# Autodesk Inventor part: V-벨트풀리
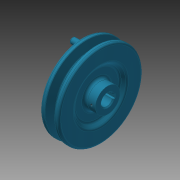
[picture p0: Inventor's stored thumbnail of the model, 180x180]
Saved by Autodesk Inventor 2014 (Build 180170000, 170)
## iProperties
Company: 한국ATC센터
Created: 2015-12
Part Number: V-벨트풀리
Document SubType Name: Modeling
Designer: mdu
Density: 7.25 g/cm^3
Mass: 596.622 g
Surface Area: 212.232 cm^2
Volume: 82.2927 cm^3
Material: 주철
Appearance: 터키옥색
Author: mdu
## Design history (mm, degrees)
sketch "스케치1"
  geometry: L1 (-13, 0)-(13, 0); L2 (-13, 0)-(-13, 12.5); L3 (-13, 12.5)-(-9, 12.5); L4 (-9, 12.5)-(-9, 23); L5 (-9, 23)-(-13, 27); L6 (-13, 27)-(-13, 42.7); L7 (-13, 42.7)-(-8.325, 42.7); L8 (-8.325, 42.7)-(-5.574, 33.7); L9 (-5.574, 33.7)-(-1.426, 33.7); L10 (-1.426, 33.7)-(1.325, 42.7); L11 (1.325, 42.7)-(6, 42.7); L12 (6, 42.7)-(6, 27); L13 (6, 27)-(2, 23); L14 (2, 23)-(2, 12.5); L15 (2, 12.5)-(13, 12.5); L16 (13, 12.5)-(13, 0); L17 (-7.5, 40)-(0.5, 40); 2 further points
  constraints: 34 end point, 6 parallel, 5 collinear, 5 equal length, 4 perpendicular, 2 point on line, 1 coincident, 1 horizontal, 1 midpoint
  dimensions: "d0" = 26 distance of L1.start L1.end; "d1" = 2.7 distance between parallel lines of L7 L17; "d2" = 6.3 distance between parallel lines of L9 L17; "d3" = 8 distance of L17.start L17.end; "d4" = 34 deg angle of L10 L8; "d5" = 19 distance between parallel lines of L12 L6; "d7" = 25 diameter of L15 L1; "d8" = 46 diameter of L13.end L1; "d9" = 54 diameter of L12.end L1; "d10" = 4 distance between parallel lines of L2 L4; "d11" = 80 diameter of L17 L1
revolve "회전1" sketch "스케치1" stored, may be unused: angle "d12" = 90 deg
sketch "스케치2"
  geometry: L1 (-2, 5.657)-(-2, 7.8); L2 (-2, 7.8)-(2, 7.8); L3 (2, 7.8)-(2, 5.657); A1 r 6 centre (0, 0) between (-2, 5.657) and (2, 5.657); 1 further point
  constraints: 6 end point, 2 parallel, 2 point on circle, 1 centre point, 1 coincident, 1 perpendicular, 1 vertical
  dimensions: "d13" = 12 diameter of A1; "d14" = 13.8 dimension on A1 L2; "d15" = 4 distance of L1.end L2.end
extrude "돌출1" cut sketch "스케치2" stored distance "d16" = 10; taper "d17" = 0 deg
node "작업 평면1"
sketch "스케치3"
  geometry: L1 (-5.5, 12.5)-(-5.5, -12.5) reference; L2 (20.5, 27)-(20.5, -27) reference; 3 further points
  constraints: 1 horizontal alignment, 1 midpoint
  dimensions: "d18" = 4 distance from line of point (-1.5, 0) L1; "d33" = 22 distance from line of point (-1.5, 0) L2 (derived)
hole "구멍1" sketch "스케치3" at (-1.5, 0) diameter "d19" = 2.459; stored, may be unused: countersink angle "d23" = 90 deg, drill point angle "d25" = 118 deg; dims "d20" = 6, "d21" = 4, "d22" = 2, "d24" = 8
fillet "모깎기1" dims "d26" = 2, "d27" = 0.5, "d28" = 1, "d29" = 3
chamfer "모따기1" distance "d30" = 1; stored, may be unused: second distance "d31" = 2, angle "d32" = 45 deg
sketch "스케치4" dims "d35" = 70
  geometry: C1 r 3 at (35, 0); 2 further points
  constraints: 2 horizontal alignment, 1 centre point, 1 coincident, 2 other
  dimensions: "d34" = 6 diameter of C1
extrude "돌출2" join sketch "스케치4" distance "d36" = 10; taper "d37" = 0 deg
fillet "모깎기2" dims "d38" = 0.5, "d39" = 1
node "솔리드1"
